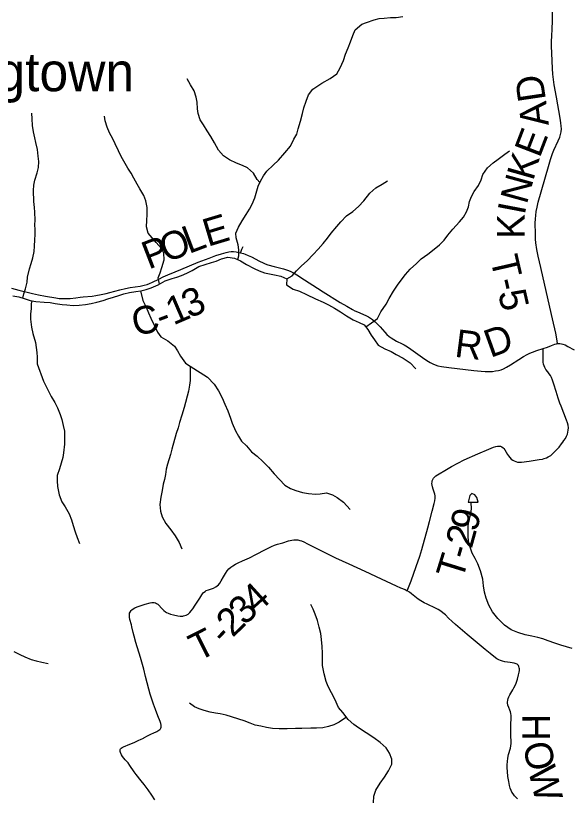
# Model space of a CAD drawing. Extents: x 1451455 to 1749751, y 218250 to 574981.
# Drawn here: x 1591778 to 1597769, y 271255 to 279706 of the extents above; entities that cross this region are included whole.
import ezdxf

# ---------------------------------------------------------------- set-up
doc = ezdxf.new("R2010")
doc.units = 0
for name, color, linetype in [('GM_X_County_Road', 7, 'Continuous'), ('GM_X_County_Road_Text', 7, 'Continuous'), ('GM_X_Minor_Lake', 7, 'Continuous'), ('GM_X_Minor_River', 7, 'Continuous'), ('GM_X_Township_Road', 7, 'Continuous'), ('GM_X_Township_Road_Text', 7, 'Continuous'), ('GM_X_Unincorporated_Text', 7, 'Continuous')]:
    doc.layers.add(name, color=color, linetype=linetype)

msp = doc.modelspace()

# ---------------------------------------------------------------- linework, layer by layer
at = {"layer": 'GM_X_County_Road'}
for points in [[(1591733.6, 276762.9), (1591812.8, 276742.2), (1591959.2, 276705.6), (1592026.4, 276690.6), (1592100.5, 276676.2), (1592210.5, 276657.7), (1592246.3, 276653.3), (1592282.3, 276651), (1592324.9, 276650.8), (1592367.4, 276653.4), (1592429.4, 276660), (1592474.9, 276665.5), (1592507.5, 276669.2), (1592605.3, 276678.8), (1592644.3, 276684.1), (1592702.4, 276694.3), (1592756.9, 276706.1), (1592795, 276715.9), (1592902.4, 276745.7), (1592966.1, 276761.1), (1593014.6, 276769.4), (1593121.6, 276786), (1593166.6, 276795.1), (1593198.2, 276803.6), (1593222.9, 276812.5), (1593255.6, 276827.6), (1593322.9, 276861.7), (1593372.6, 276886.9), (1593420.1, 276909), (1593499.6, 276939.9), (1593560.8, 276963.7), (1593751.2, 277043.9), (1593867.2, 277089.4), (1593941.1, 277116.3), (1594000.5, 277135.3), (1594051, 277149.1), (1594080, 277155), (1594106, 277158.1), (1594132.2, 277158), (1594161.4, 277154.4), (1594207.4, 277145.3)], [(1594207.4, 277145.3), (1594238.3, 277137.6), (1594257, 277131.5), (1594290.4, 277117.9), (1594326.1, 277101.5), (1594412.9, 277055.4), (1594450.1, 277036.1), (1594473.1, 277026.7), (1594501.4, 277017.3), (1594571.6, 276997.3), (1594669.5, 276973.5), (1594713.4, 276959.6), (1594744.2, 276947.3), (1594773.5, 276932.4), (1594815.7, 276906.9), (1594898.5, 276855.5), (1595039, 276762.2), (1595099.4, 276723.4), (1595283.7, 276610.1), (1595354, 276568.4), (1595417, 276533.9), (1595443.1, 276520.6), (1595469.5, 276507.8), (1595559.5, 276468.2), (1595583, 276456.9)], [(1595583, 276456.9), (1595589.3, 276453.8), (1595612.2, 276440.5), (1595633.6, 276425.2), (1595661.1, 276401.8), (1595684.5, 276379), (1595715, 276344.9), (1595763.9, 276288.2), (1595788.8, 276262.8), (1595810.7, 276243.7), (1595834, 276226.4), (1595861.5, 276209.4), (1595893.2, 276192.9), (1595952.3, 276164.5), (1595975.4, 276151.8), (1596009.3, 276131.6), (1596047.3, 276105.6), (1596172, 276015.4), (1596220.7, 275982.6), (1596256.8, 275960.6), (1596282.5, 275946.8), (1596309.1, 275935.3), (1596336.8, 275926.8), (1596377.9, 275918.2), (1596455.3, 275906.5), (1596727.7, 275875.1), (1596805.5, 275866.2), (1596850.9, 275863.1), (1596886.6, 275862.7), (1596928.6, 275865.7), (1596960.8, 275869.5), (1596992.6, 275875.7), (1597020.5, 275883.7), (1597047.7, 275893.8), (1597079.6, 275909.2), (1597123.9, 275936.5), (1597211.9, 275993.6), (1597262.4, 276024.4), (1597302.6, 276046.9), (1597332.1, 276061.6), (1597359.3, 276073.4), (1597408.8, 276091), (1597475.3, 276113)], [(1597475.3, 276113), (1597521.1, 276128.2), (1597566.2, 276144.8), (1597603.3, 276159.1), (1597619.5, 276163.7), (1597629.2, 276165.1)], [(1597629.2, 276165.1), (1597639.7, 276166.7), (1597656.7, 276166.7), (1597673.6, 276164.5), (1597690, 276160.2), (1597711.7, 276151.3), (1597744, 276134.6), (1597810, 276098.1)]]:
    msp.add_lwpolyline(points, dxfattribs=at)
at = {"layer": 'GM_X_Minor_Lake'}
for points in [[(1596773.4, 274453.7), (1596760, 274502), (1596738.4, 274530.5), (1596704.6, 274545), (1596684.3, 274525.2), (1596665.2, 274453.3)], [(1596665.2, 274453.3), (1596773.4, 274453.7)]]:
    msp.add_lwpolyline(points, dxfattribs=at)
at = {"layer": 'GM_X_Minor_River'}
for points in [[(1594177.6, 277073.7), (1594188.5, 277112.7), (1594187.3, 277176.8), (1594182, 277230.9), (1594160.9, 277307.3), (1594157.6, 277359.4), (1594186.4, 277423.1), (1594225.3, 277492.7), (1594266.2, 277558.2), (1594304.9, 277615.7), (1594331.6, 277669.4), (1594360.5, 277739.1), (1594398.1, 277864.7), (1594422.9, 277920.5), (1594455.6, 277976.1), (1594492.3, 278027.7), (1594559.1, 278092.8), (1594615.9, 278146.1), (1594686.9, 278225.2), (1594745.9, 278298.5), (1594782.9, 278372.1), (1594813.5, 278425.7), (1594830.3, 278483.6), (1594855.4, 278567.3), (1594876.4, 278651.2), (1594891.2, 278711), (1594914.2, 278784.8), (1594941, 278850.5), (1594987.8, 278914), (1595086.7, 278976.7), (1595175.5, 279029.5), (1595246.1, 279078.6), (1595283, 279144.2), (1595318, 279223.8), (1595340.9, 279289.6), (1595369.8, 279357.3), (1595394.6, 279423), (1595421.5, 279492.7), (1595446.3, 279552.5), (1595517.1, 279615.6), (1595569.4, 279630.9), (1595649.8, 279661.8), (1595706, 279675.1), (1595760.2, 279680.3), (1595828.3, 279685.4), (1595886.3, 279686.6), (1595960.6, 279697.6)], [(1594415.9, 277904.9), (1594385, 277937), (1594347.9, 278005.6), (1594282.5, 278064.6), (1594228.8, 278087.3), (1594165.1, 278114.2), (1594089.5, 278151.3), (1594023.9, 278192.3), (1593970.7, 278255.1), (1593927.6, 278333.8), (1593884.5, 278402.5), (1593847.2, 278463), (1593808, 278527.7), (1593772.6, 278582.2), (1593749.4, 278648.6), (1593742.1, 278700.8), (1593737, 278770.9), (1593729.6, 278825.1), (1593704.5, 278895.5), (1593665.3, 278960.1), (1593632, 279022.7)], [(1591856.8, 276655.8), (1591865.3, 276704), (1591886, 276757.8), (1591900.9, 276827.6), (1591907.6, 276883.6), (1591928.8, 276973.5), (1591945.5, 277031.3), (1591964.3, 277093.1), (1591977.2, 277159), (1591981.9, 277219), (1591984.8, 277287.1), (1591987.5, 277345.1), (1591988.2, 277397.2), (1591986.8, 277449.2), (1591989.5, 277499.3), (1591984.5, 277583.4), (1591981.1, 277633.5), (1591976, 277699.7), (1591969.5, 277819.9), (1591974.2, 277875.9), (1591986.9, 277929.8), (1592009.9, 278007.6), (1592026.6, 278067.5), (1592029.4, 278131.5), (1592022.2, 278189.7), (1592013, 278259.9), (1591996, 278338.2), (1591986.6, 278388.4), (1591971.4, 278450.7), (1591960.3, 278520.9), (1591955.2, 278591.1), (1591954, 278655.2)], [(1593332.9, 276808.6), (1593318.7, 276874.3), (1593339.5, 276930.1), (1593358.2, 276985.9), (1593381.3, 277069.7), (1593378.2, 277141.8), (1593352.8, 277192.3), (1593295.5, 277257.1), (1593210.7, 277356.4), (1593191.6, 277426.8), (1593194.4, 277494.8), (1593197.3, 277558.8), (1593198.2, 277634.9), (1593183.1, 277707.2), (1593163.8, 277765.6), (1593118.7, 277836.3), (1593091.3, 277886.7), (1593056.1, 277951.3), (1593026.7, 278005.7), (1592989.4, 278058.3), (1592918.9, 278185.4), (1592887.6, 278247.9), (1592854.6, 278322.5), (1592827.2, 278376.9), (1592790, 278441.5), (1592764.8, 278503.9), (1592743.6, 278570.3), (1592736.2, 278622.5)], [(1595559.6, 276345), (1595620.6, 276388.2), (1595685.3, 276437.3), (1595724.2, 276508.9), (1595779.3, 276592.3), (1595812.1, 276653.9), (1595859.1, 276731.3), (1595904, 276794.8), (1595942.7, 276850.4), (1595989.5, 276911.8), (1596038.3, 276969.2), (1596107.1, 277030.3), (1596159.8, 277081.7), (1596230.5, 277130.8), (1596281.1, 277172.1), (1596355.9, 277233.2), (1596406.6, 277282.6), (1596447.3, 277336.1), (1596500.1, 277401.5), (1596573.2, 277478.6), (1596615.9, 277532), (1596648.6, 277589.7), (1596669.3, 277641.5), (1596680.1, 277701.4), (1596700.7, 277753.2), (1596731.4, 277806.8), (1596776.3, 277872.3), (1596805.1, 277932), (1596823.8, 277989.8), (1596874.8, 278063.2), (1596937.5, 278116.4), (1596988, 278155.8), (1597060.8, 278210.9), (1597113.3, 278248.2)], [(1594707.8, 276865.3), (1594764.3, 276898.5), (1594813, 276949.9), (1594865.7, 277005.3), (1594926.5, 277060.5), (1594991.4, 277125.7), (1595046.1, 277185), (1595098.9, 277244.4), (1595145.7, 277303.8), (1595184.4, 277357.3), (1595245.4, 277428.6), (1595290.1, 277480), (1595352.9, 277545.3), (1595421.6, 277590.4), (1595482.3, 277645.6), (1595539.1, 277706.9), (1595604.2, 277788.1), (1595667, 277847.3), (1595737.6, 277888.4), (1595796.1, 277923.7)], [(1591749, 276681.5), (1591810.9, 276668.7), (1591870.7, 276651.8), (1591934.5, 276631), (1591996.4, 276618.1), (1592084.4, 276610.9), (1592150.4, 276608), (1592204.3, 276599.2), (1592280.3, 276588.2), (1592332.2, 276583.5), (1592398.2, 276576.6), (1592464.3, 276579.7), (1592532.5, 276588.8), (1592592.6, 276598), (1592654.9, 276611.1), (1592723.2, 276632.2), (1592775.4, 276647.5), (1592835.7, 276666.7), (1592892, 276686), (1592948.3, 276703.2), (1593008.5, 276716.4), (1593076.7, 276727.5), (1593130.9, 276736.8), (1593189.1, 276750), (1593243.3, 276767.2), (1593317.8, 276800.3), (1593392.4, 276841.3), (1593466.8, 276868.3), (1593519, 276881.6), (1593569.3, 276898.9), (1593627.6, 276924.2), (1593686.1, 276955.4), (1593756.7, 276996.5), (1593825, 277019.6), (1593893.3, 277040.7), (1593943.6, 277056), (1593999.9, 277079.2), (1594068.2, 277098.3), (1594142.2, 277089.3), (1594207.9, 277060.4), (1594271.4, 277019.4), (1594352.9, 276976.3), (1594406.7, 276951.5), (1594464.5, 276930.7), (1594520.3, 276917.9), (1594572.2, 276907.2), (1594642.1, 276892.2), (1594707.8, 276865.3), (1594703, 276801.2), (1594776.5, 276754.2), (1594842.3, 276733.2), (1594919.9, 276694.1), (1595015.4, 276648.8), (1595101, 276611.6), (1595156.7, 276584.8), (1595222.3, 276547.8), (1595287.8, 276506.9), (1595351.3, 276464), (1595424.9, 276420.9), (1595488.6, 276392), (1595542.3, 276367.2), (1595581.7, 276316.6), (1595619, 276258), (1595654.4, 276205.5), (1595693.7, 276148.9), (1595767.2, 276109.8), (1595834.9, 276078.9), (1595886.6, 276048.1), (1595964.2, 276009)], [(1593125.7, 276735.9), (1593151.6, 276632.3), (1593186.7, 276559.8), (1593211.9, 276497.3), (1593237.2, 276438.9), (1593276.2, 276356.3), (1593309.4, 276289.8), (1593346.8, 276237.2), (1593422.3, 276194.1), (1593493.6, 276137), (1593527, 276086.5), (1593560.3, 276030), (1593611.4, 275955.2), (1593663.1, 275920.4)], [(1591951.5, 276627.4), (1591946, 276594.8), (1591947.4, 276540.7), (1591938.7, 276486.7), (1591940, 276428.6), (1591948.9, 276342.4), (1591964.1, 276276.1), (1591990.8, 276175.6), (1592000.1, 276121.4), (1592007.5, 276069.3), (1592010.9, 276019.1), (1592012, 275947)], [(1592012, 275947), (1592079.6, 275761.1), (1592118.5, 275680.3), (1592161.3, 275595.4), (1592202.4, 275528.6), (1592229.6, 275472), (1592258.6, 275401.4), (1592277.8, 275347), (1592292.9, 275282.6), (1592304, 275220.2), (1592307.2, 275168), (1592305.9, 275077.8), (1592296.6, 274985.6), (1592287.9, 274935.6), (1592269, 274875.7), (1592250, 274811.8), (1592226.9, 274739.9), (1592226.1, 274681.8), (1592229.3, 274623.6), (1592248, 274533), (1592276.9, 274458.4), (1592314.1, 274401.7), (1592357.1, 274326.8), (1592380.2, 274262.3), (1592399.3, 274199.8), (1592420.3, 274131.3), (1592441.5, 274072.8), (1592466.5, 274006.3)], [(1595964.2, 276009), (1596039.6, 275957.9), (1596100.8, 275893)], [(1593663.1, 275920.4), (1593661.3, 275767.7), (1593656.6, 275715.6), (1593643.6, 275651.6), (1593597, 275475.8), (1593571.8, 275393.9), (1593546.6, 275314.1), (1593531.8, 275256.1), (1593510.9, 275196.2), (1593464.3, 275024.4), (1593449.5, 274966.5), (1593418, 274864.6), (1593405.1, 274808.7), (1593396.3, 274752.6), (1593385.5, 274698.6), (1593372.7, 274646.7), (1593359.8, 274580.7), (1593344.7, 274506.7), (1593335.5, 274428.6), (1593342.5, 274356.3), (1593359.6, 274293.9), (1593398.6, 274223.1), (1593455.7, 274156), (1593502.8, 274089.1), (1593543.8, 274016.3), (1593572.8, 273947.7)], [(1593663.1, 275920.4), (1593852, 275802.9), (1593921, 275725.7), (1593968, 275654.8), (1594006.9, 275578), (1594036, 275511.3), (1594068.9, 275438.6), (1594099.8, 275360), (1594117.1, 275305.5), (1594153.9, 275224.8), (1594185.1, 275164.1), (1594218.4, 275113.5), (1594271.7, 275060.5), (1594326.8, 274997.5), (1594388.2, 274950.5), (1594449.4, 274893.4), (1594510.5, 274830.3), (1594571.6, 274759.2), (1594685.9, 274637.1), (1594745.5, 274602.1), (1594805.2, 274579.2), (1594875, 274558.1), (1594942.9, 274547), (1595016.8, 274539.9), (1595066.9, 274543.2), (1595135.2, 274554.2), (1595198.9, 274531.2), (1595250.6, 274504.3), (1595317.9, 274453.2), (1595392.8, 274373.8)], [(1597789.4, 272872.3), (1597727.6, 272891.2), (1597667.8, 272908.1), (1597600.1, 272931.2), (1597530.4, 272956.3), (1597472.6, 272977.2), (1597416.8, 272992), (1597352.9, 273005), (1597283.1, 273022.1), (1597203.4, 273047.3), (1597131.7, 273074.5), (1597058.4, 273125.7), (1596987.3, 273196.9), (1596928.3, 273268), (1596887.3, 273340.8), (1596858.4, 273417.5), (1596843.3, 273481.9), (1596832.3, 273550.2), (1596823.3, 273622.6), (1596800.6, 273713.2), (1596769.7, 273785.8), (1596740.5, 273844.4), (1596709.3, 273901), (1596686.2, 273965.6), (1596671.1, 274030), (1596665.9, 274088.2), (1596666.8, 274148.4), (1596665.6, 274202.6), (1596676.5, 274262.6), (1596691.3, 274314.5), (1596702.2, 274376.5), (1596699.7, 274453.4)], [(1595761.2, 271484), (1595804.2, 271553.6), (1595841.3, 271625.2), (1595840.1, 271677.4), (1595815, 271742), (1595779.8, 271798.6), (1595716.6, 271857.8), (1595645.3, 271909), (1595563.9, 271962.3), (1595480.6, 272015.7), (1595429.1, 272052.6), (1595369.8, 272105.6), (1595312.9, 272182.7), (1595265.6, 272237.5), (1595224.9, 272324.4), (1595189.8, 272393.1), (1595152.8, 272463.9), (1595131.6, 272518.3), (1595110.7, 272598.9), (1595094, 272689.4), (1595093, 272757.6), (1595092, 272823.8), (1595087, 272894.1), (1595082.1, 272968.4), (1595073.1, 273036.7), (1595058, 273105.1), (1595037, 273173.6), (1595012, 273242.2), (1594990.8, 273296.7), (1594967.5, 273347.2)], [(1591756.9, 272841.3), (1591822.5, 272808.2), (1591878.1, 272781.3), (1591945.8, 272754.3), (1591999.7, 272741.4), (1592059.5, 272724.5), (1592129.3, 272709.4)], [(1595351.8, 272130.1), (1595273.3, 272076.9), (1595214.9, 272049.7), (1595158.5, 272030.5), (1595096.3, 272017.4), (1595026.1, 272012.4), (1594968.1, 272011.3), (1594870, 272010.7), (1594801.8, 272007.7), (1594709.7, 272005.1), (1594623.6, 272004.4), (1594553.6, 272007.4), (1594487.7, 272018.4), (1594427.8, 272033.4), (1594364, 272046.4), (1594312.2, 272067.2), (1594246.5, 272090.2), (1594188.7, 272111.1), (1594109, 272134.4), (1594051.2, 272153.3), (1593987.3, 272168.3), (1593935.4, 272175.1), (1593879.5, 272184), (1593813.7, 272205), (1593761.9, 272219.8), (1593710.2, 272244.6), (1593654.7, 272281.6)], [(1595645, 271204.9), (1595646.1, 271277.1), (1595667.1, 271345), (1595714.2, 271418.5), (1595761.2, 271484)]]:
    msp.add_lwpolyline(points, dxfattribs=at)
at = {"layer": 'GM_X_Township_Road'}
for points in [[(1597629.2, 276165.1), (1597625.3, 276192.7), (1597619.2, 276236.7), (1597611.5, 276278.6), (1597575.9, 276431.9), (1597529.1, 276636.2), (1597449.4, 276988.2), (1597422.1, 277109.8), (1597408.4, 277180.7), (1597397.7, 277252.1), (1597394.2, 277291.2), (1597391.3, 277350.1), (1597390, 277465), (1597391.7, 277510.9), (1597395.2, 277550.1), (1597401.2, 277592.3), (1597410.1, 277637.4), (1597423.2, 277691.6), (1597532.9, 278076.6), (1597555.7, 278152), (1597577.9, 278217.2), (1597592.5, 278253.7), (1597637.8, 278355.4), (1597654.2, 278394.9), (1597662.9, 278423), (1597669.3, 278451.8), (1597672.1, 278484.5), (1597670.5, 278513.9), (1597666.3, 278549.8), (1597658.6, 278598.4), (1597619.7, 278828), (1597595.9, 278959.8), (1597586.4, 279017.9), (1597580.3, 279073.3), (1597576.2, 279135.5), (1597568.4, 279302.5), (1597566.7, 279377.9), (1597567.5, 279436.9), (1597569, 279478.6), (1597572.9, 279572), (1597575.3, 279640.7), (1597575.4, 279743.8)], [(1594207.4, 277145.3), (1594214.4, 277163.8), (1594222.3, 277184.8), (1594235.2, 277214)], [(1596007.5, 273496.7), (1596036.9, 273568.6), (1596050.6, 273602), (1596105.6, 273759.9), (1596143.6, 273871.6), (1596165.2, 273940.4), (1596229.5, 274177.2), (1596247.1, 274243.8), (1596276.8, 274354.6), (1596299.2, 274437), (1596305.9, 274469), (1596308.9, 274495), (1596308.7, 274521.2), (1596305.5, 274540.6), (1596299.7, 274562.7), (1596288.3, 274593.5), (1596279.6, 274618.2), (1596275.4, 274637.3), (1596273.9, 274653.6), (1596275.4, 274669.8), (1596278.6, 274682.5), (1596284.6, 274697.7), (1596292.9, 274711.9), (1596303.3, 274724.4), (1596318.1, 274737.3), (1596334.4, 274748.5), (1596433.3, 274806.7), (1596487.3, 274837.8), (1596553.7, 274873.6), (1596624.2, 274908.4), (1596770.3, 274975), (1596887.8, 275025.2), (1596939.3, 275046.3), (1596964.3, 275054.3), (1596983.4, 275058.2), (1596999.6, 275059), (1597015.6, 275056.7), (1597030.6, 275050.5), (1597043.6, 275040.8), (1597050.4, 275033.8), (1597062.2, 275018), (1597077, 274992.3), (1597090.1, 274969.5), (1597101.2, 274953.2), (1597115.5, 274935.2), (1597131.7, 274918.9), (1597147.2, 274906.8), (1597161.1, 274898.3), (1597179.1, 274890.6), (1597198.2, 274885.9), (1597217.8, 274884.6), (1597240.7, 274886.3), (1597325.2, 274897.1), (1597432.4, 274912.5), (1597467.8, 274919.1), (1597486.8, 274924.4), (1597511.4, 274933.4), (1597529.2, 274941.9), (1597557.4, 274958.6), (1597580.2, 274977.2), (1597599.2, 274995.4), (1597648.1, 275047), (1597675.4, 275083.1), (1597688.2, 275102.2), (1597700, 275117.9), (1597716.5, 275142.2), (1597728.7, 275165.2), (1597736.9, 275186.5), (1597743.2, 275208.3), (1597747.1, 275230.8), (1597747.8, 275257), (1597744.8, 275283), (1597738.8, 275308.5), (1597728.4, 275339.7), (1597669.3, 275489.1), (1597656.4, 275522.8), (1597637.8, 275575.3), (1597615, 275646.9), (1597591.7, 275727.9), (1597578.1, 275771.4), (1597566.6, 275798.5), (1597553.5, 275821.1), (1597540.4, 275840), (1597524.5, 275860.8), (1597505.3, 275887.2), (1597494.3, 275907.1), (1597486.9, 275925.2), (1597481, 275943.9), (1597477.2, 275963.2), (1597475.5, 275982.8), (1597475.4, 276038.4), (1597475.3, 276113)], [(1593013.9, 273267), (1593025.1, 273282.7), (1593034.6, 273291.7), (1593048, 273301.2), (1593065.2, 273310.6), (1593089, 273321.5), (1593175.9, 273351.4), (1593232.6, 273367.7), (1593248.7, 273370.2), (1593261.9, 273370.4), (1593274.9, 273368.8), (1593287.5, 273365.1), (1593299.3, 273359.6), (1593313, 273350.6), (1593325.3, 273339.7), (1593354.4, 273308.5), (1593379.7, 273282.8), (1593397.5, 273268.5), (1593405.8, 273263.3), (1593426.1, 273252.9), (1593450.9, 273244.2), (1593482.6, 273235.8), (1593530.7, 273225.9), (1593556.8, 273222.9), (1593583.1, 273223.5), (1593592.5, 273224.7), (1593620.4, 273233.2), (1593641, 273243.4), (1593660.1, 273261.2), (1593674.8, 273278.9), (1593692.2, 273302.8), (1593717.7, 273341), (1593768.2, 273417.7), (1593788.4, 273451.4), (1593797.7, 273464.7), (1593808.6, 273476.8), (1593823.8, 273489.2), (1593837.5, 273497.8), (1593861.1, 273508.2), (1593883.3, 273513.5), (1593914.3, 273524), (1593940.2, 273537.8), (1593955.6, 273549.9), (1593967.5, 273561.1), (1593982.4, 273578.7), (1593999.3, 273602.8), (1594022.5, 273646.1), (1594042.9, 273683.4), (1594060.9, 273710.5), (1594080.3, 273732.5), (1594102.2, 273751.9), (1594123.6, 273766.6), (1594151.8, 273783.1), (1594181.1, 273797.6), (1594229.2, 273818.3), (1594280.3, 273840.5), (1594304, 273851.7), (1594373.6, 273888), (1594477.2, 273943.2), (1594541.8, 273974.8), (1594575.1, 273988.7), (1594606.2, 273999), (1594662.9, 274015.2), (1594725.4, 274034.4), (1594760.1, 274043.3), (1594782.8, 274046.5), (1594799, 274047.4), (1594825, 274045.7), (1594847.3, 274040.4), (1594865.9, 274034.3), (1594890.2, 274024.1), (1594931.2, 274003.3), (1595054, 273941.1), (1595233.8, 273853.2), (1595376.3, 273786.1), (1595549.3, 273706.9), (1595725.5, 273626.9), (1595888.6, 273549.8), (1595936.3, 273528.2), (1595985.1, 273509.4), (1596007.5, 273496.7)], [(1597126.8, 272006.6), (1597128.1, 272047.7), (1597130.6, 272122.9), (1597130.2, 272149), (1597127.4, 272171.5), (1597122.4, 272190.3), (1597116.7, 272205.4), (1597103.7, 272235.3), (1597093.9, 272262.8), (1597090.9, 272285.4), (1597090.9, 272295.1), (1597092.8, 272314.6), (1597097.8, 272333.6), (1597104.8, 272352), (1597115, 272372.6), (1597147.5, 272426), (1597160.4, 272448.8), (1597171.9, 272472.4), (1597183, 272499.7), (1597198, 272543.1), (1597210.9, 272587.1), (1597217.3, 272615.9), (1597219.6, 272635.4), (1597219.4, 272651.8), (1597217.2, 272664.7), (1597211.9, 272680.2), (1597207.8, 272688.4), (1597201.5, 272695.9), (1597194, 272702.3), (1597185.7, 272707.5), (1597173.5, 272712.4), (1597160.8, 272715.4), (1597118.5, 272720.5), (1597063.4, 272729.2), (1597037.9, 272735.3), (1597016.2, 272742.6), (1596995.3, 272752), (1596975.6, 272763.1), (1596960.3, 272773.9), (1596902.1, 272818.3), (1596848.9, 272861.9), (1596697.5, 272987.2), (1596655.6, 273023.9), (1596578.4, 273089.8), (1596529, 273132.5), (1596492.7, 273165.6), (1596454.8, 273201.9), (1596419.3, 273236), (1596391.9, 273259.3), (1596370.7, 273274.8), (1596343, 273292.3), (1596311.3, 273309.5), (1596221.7, 273350.2), (1596189.5, 273366.4), (1596155.4, 273386.1), (1596125.4, 273406.1), (1596088.9, 273434), (1596054, 273463.9), (1596030.3, 273483), (1596007.5, 273496.7)], [(1593279.6, 271240.4), (1593250.4, 271287.5), (1593210, 271346.7), (1593167.4, 271404.6), (1593134.9, 271445.7), (1593080.4, 271511.1), (1593059.1, 271540.1), (1593011.7, 271610.8), (1592992.5, 271637.3), (1592962.6, 271672), (1592933.7, 271707.6), (1592920.8, 271726.4), (1592909.2, 271749.1), (1592905.9, 271761.5), (1592905.5, 271771.2), (1592906.7, 271780.8), (1592911.1, 271789.6), (1592917.2, 271797.1), (1592928.1, 271804.2), (1592942.9, 271811.2), (1593012.6, 271839.6), (1593058, 271858.5), (1593108.3, 271882.3), (1593126.1, 271890.8), (1593158.8, 271906.1), (1593161.3, 271908.1), (1593202, 271928.9), (1593222.4, 271939), (1593245.8, 271950.2), (1593263.5, 271958.6), (1593301.4, 271977.2), (1593323.9, 271990.2), (1593334.4, 271997.9), (1593341.2, 272005), (1593346.4, 272013.3), (1593349.6, 272022.5), (1593351, 272032.2), (1593350.7, 272045.4), (1593347.5, 272061.4), (1593340.1, 272083.2), (1593314.1, 272146.5), (1593288.8, 272213.2), (1593267.3, 272270.9), (1593240, 272347.6), (1593230, 272378.8), (1593215.2, 272432.5), (1593181.2, 272572), (1593161.8, 272651.3), (1593127.6, 272774.4), (1593077.2, 272937.2), (1593057.1, 273006.4), (1593047.2, 273044.5), (1593032.4, 273108.2), (1593027.8, 273127.2), (1593012.8, 273187), (1593007.6, 273212.4), (1593006.1, 273228.8), (1593006.9, 273241.8), (1593009.5, 273254.6), (1593013.9, 273267)], [(1597198.2, 271248.2), (1597167.3, 271281.9), (1597151.1, 271302.4), (1597138.7, 271321.6), (1597129.9, 271339.1), (1597120.8, 271363.5), (1597112.2, 271394.9), (1597103.6, 271436.5), (1597095.2, 271491.4), (1597089.6, 271543.4), (1597087, 271585.7), (1597087.2, 271618.4), (1597089.8, 271654.1), (1597095, 271689.7), (1597103.1, 271728.1), (1597122.3, 271797.5), (1597127.6, 271823), (1597130.4, 271848.9), (1597130.6, 271875), (1597126.9, 271923.7), (1597125.3, 271959.5), (1597126.6, 271998.6), (1597126.8, 272006.6)]]:
    msp.add_lwpolyline(points, dxfattribs=at)

# ---------------------------------------------------------------- texts
at = {"layer": 'GM_X_County_Road_Text'}
for s, rotation, p in [('E', 16.75732, (1593853.6, 277209.4)), ('O', 21.15167, (1593403.3, 277036.4)), ('L', 20.78728, (1593649.1, 277131.5)), ('P', 21.15443, (1593214.6, 276963.4)), ('3', 23.72456, (1593653.2, 276434)), ('1', 23.31261, (1593481.3, 276360)), ('C', 12.89552, (1593069.3, 276243)), ('-', 20.69644, (1593352.2, 276310.8)), ('R', 352.69442, (1596510.9, 276024.4)), ('D', 19.82294, (1596905.5, 276009.5))]:
    msp.add_text(s, height=300, rotation=rotation, dxfattribs=at).set_placement(p)
at = {"layer": 'GM_X_Township_Road_Text'}
for s, rotation, p in [('D', 98.48822, (1597506.3, 278799.4)), ('A', 96.54958, (1597537.9, 278526.2)), ('E', 69.00079, (1597437.8, 278161.9)), ('K', 74.17569, (1597368.1, 277914.7)), ('N', 74.52746, (1597297.8, 277660.7)), ('I', 79.16348, (1597276.1, 277546)), ('K', 89.78871, (1597276.5, 277296.6)), ('T-5', 282.91828, (1596902.3, 277084.6)), ('9', 74.56706, (1596753.3, 274121.2)), ('2', 74.49385, (1596703.7, 273942.7)), ('-', 74.23113, (1596669.9, 273822.7)), ('T', 72.81976, (1596601.3, 273600.6)), ('4', 42.25023, (1594384.6, 273240.3)), ('3', 44.24051, (1594254.2, 273113.3)), ('2', 44.21804, (1594121.7, 272984.3)), ('T', 26.81996, (1593748.9, 272728.2)), ('-', 46.7047, (1594039.6, 272897.1)), ('H', 270.10929, (1597249.2, 272165.6)), ('O', 281.31226, (1597256.1, 271838)), ('W', 283.54466, (1597310.6, 271566.6))]:
    msp.add_text(s, height=300, rotation=rotation, dxfattribs=at).set_placement(p)
at = {"layer": 'GM_X_Unincorporated_Text'}
msp.add_text('Stringtown', height=417, rotation=0.00001, dxfattribs=at).set_placement((1590423.8, 278890.4))

doc.saveas('drawing.dxf')
